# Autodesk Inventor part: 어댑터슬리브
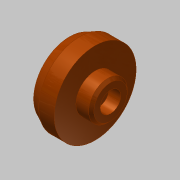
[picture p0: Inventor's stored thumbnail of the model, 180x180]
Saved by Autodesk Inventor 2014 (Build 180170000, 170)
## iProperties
Created: 2016-06
Part Number: 어댑터슬리브
Material: 강철, 탄소
Document SubType Name: Modeling
Designer: mduedu
Density: 7.87 g/cm^3
Appearance: 매끄러움 - 연한 주황색
Author: mduedu
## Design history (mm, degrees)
sketch "스케치2"
  geometry: L1 (0, 0)-(0, 14); L2 (0, 14)-(-4, 16); L3 (-4, 16)-(-10, 16); L4 (-10, 16)-(-10, 7.5); L5 (-10, 7.5)-(-16, 7.5); L6 (-16, 7.5)-(-16, 0); L7 (-16, 0)-(0, 0)
  constraints: 14 end point, 4 parallel, 1 perpendicular, 1 vertical
  dimensions: "d0" = 32 diameter of L3 L7; "d2" = 28 diameter of L1.end L7; "d3" = 6 distance of L2.end L3.end; "d4" = 6 distance of L4.end L5.end; "d5" = 15 diameter of L5 L7; "d6" = 16 distance between parallel lines of L6 L1
revolve "회전1" sketch "스케치2" stored, may be unused: angle "d7" = 90 deg
sketch "스케치3"
  geometry: L1 (-16, -7.5)-(-16, 7.5) reference; L2 (-16, 7.5)-(-10, 7.5) reference; L3 (-10, 7.5)-(-10, 16) reference; L4 (-10, 16)-(-4, 16) reference; L5 (-4, 16)-(0, 14) reference; L6 (0, 14)-(0, -14) reference; L7 (0, -14)-(-4, -16) reference; L8 (-4, -16)-(-10, -16) reference; L9 (-10, -16)-(-10, -7.5) reference; L10 (-10, -7.5)-(-16, -7.5) reference; L11 (0, 10)-(-5, 10); L12 (-5, 10)-(-5, 8); L13 (-5, 8)-(-7, 6); L14 (-7, 6)-(-7, 0); L15 (-7, 0)-(0, 0); L16 (0, 10)-(0, 0)
  constraints: 12 end point, 3 parallel, 2 perpendicular, 1 point on line
  dimensions: "d8" = 20 diameter of L11 L15; "d10" = 16 diameter of L12.end L15; "d11" = 12 diameter of L13.end L15; "d12" = 9 distance between parallel lines of L14 L1; "d13" = 2 distance between parallel lines of L12 L14
revolve "회전2" sketch "스케치3" stored, may be unused: angle "d14" = 90 deg
chamfer "모따기1" distance "d15" = 1; stored, may be unused: second distance "d16" = 2, angle "d17" = 45 deg
sketch "스케치4"
  geometry: 2 further points
  constraints: 1 coincident
sketch "스케치5"
  geometry: 1 further point
hole "구멍1" sketch "스케치5" at (0, 0) diameter "d18" = 4.5; stored, may be unused: countersink angle "d22" = 90 deg, drill point angle "d24" = 0 deg; dims "d19" = 6, "d20" = 8, "d21" = 4.6, "d23" = 8
node "솔리드1"
node "절단 모서리 투영1"
